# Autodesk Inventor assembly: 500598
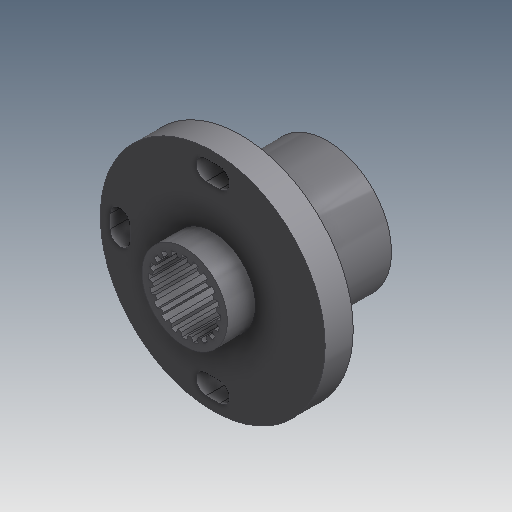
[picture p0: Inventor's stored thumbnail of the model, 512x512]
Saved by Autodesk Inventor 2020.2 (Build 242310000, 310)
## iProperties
Created: 2000-02
Part Number: 500598
Document SubType Name: Assembly
Designer: sspink
Mass: 1254.93 g
Surface Area: 444.186 cm^2
Volume: 159.985 cm^3
Density: 7.84403 g/cm^3
Control State: 0
Checked Out: False
Master: False
Shininess: 0.0
Length Units: 11272
Angle Units: 11279
Time Units: 11290
Mass Units: 11286
Length Display Precision: 3
Angle Display Precision: 2
Compacted: True
Dimensions: 3,9x2,5x3,9 in
Mass: 2,767 lb
Density: 0.0
Volumn: 0.0
Area: 0.0
PropertySet Name: Model Information
Author: sspink
Revision Number: -
Title: 500598
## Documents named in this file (4)
- D:\07 - DEMODATEN\OTX 2019 - Dataset - UPDATE - Dez2019\Designs\07-Packing machine\500598.iam
- D:\07 - DEMODATEN\OTX 2019 - Dataset - UPDATE - Dez2019\Designs\07-Packing machine\Parts\ADSK-011558.ipt
- D:\07 - DEMODATEN\OTX 2019 - Dataset - UPDATE - Dez2019\Designs\07-Packing machine\Parts\ADSK-011557.ipt
- D:\07 - DEMODATEN\OTX 2019 - Dataset - UPDATE - Dez2019\Content Center Files\de-DE\ISO 4026\ISO 4026 - M10 x 12 - ISO.ipt
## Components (4 placed, 3 different names)
1. ADSK-011557:1 — Flush:1, Passend:1, Passend:2, Tangential:1, Tangential:2
2. ADSK-011558:1 — Flush:1
3. ISO 4026 M10 x 12:1 — Passend:2, Tangential:1
4. ISO 4026 M10 x 12:2 — Passend:1, Tangential:2
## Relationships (5: Mate 2, Tangent 2, Flush 1)
- Flush:1: ADSK-011557:1 ↔ ADSK-011558:1
- Passend:1 [Mate]: ADSK-011557:1 ↔ ISO 4026 M10 x 12:2
- Passend:2 [Mate]: ADSK-011557:1 ↔ ISO 4026 M10 x 12:1
- Tangential:1: ADSK-011557:1 ↔ ISO 4026 M10 x 12:1
- Tangential:2: ADSK-011557:1 ↔ ISO 4026 M10 x 12:2
